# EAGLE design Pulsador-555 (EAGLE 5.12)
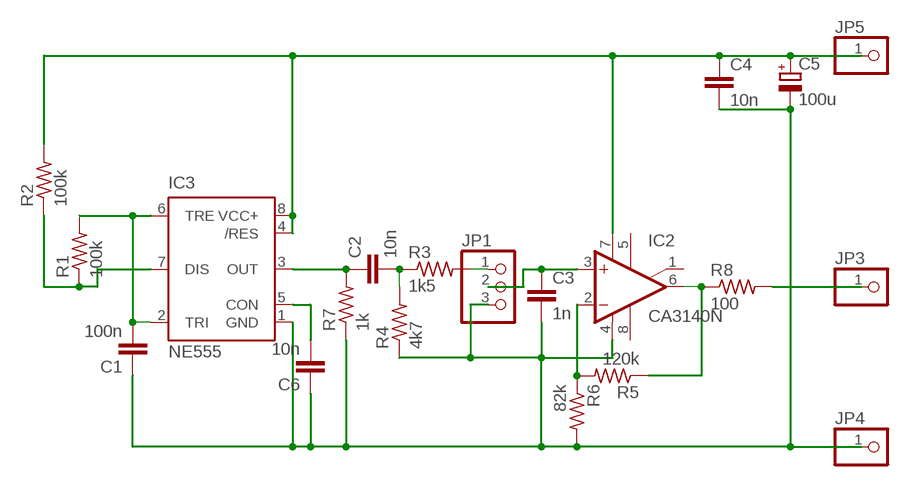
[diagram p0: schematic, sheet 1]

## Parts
C1  100n  C-EU050-024X044  [C050-024X044]
C2  10n  C-EU050-024X044  [C050-024X044]
C3  1n  C-EU050-024X044  [C050-024X044]
C4  10n  C-EU025-025X050  [C025-025X050]
C5  100u  CPOL-EUE3.5-10  [E3,5-10]
C6  10n  C-EU050-024X044  [C050-024X044]
IC2  CA3140N  [DIL08]
IC3  NE555  [DIL-08]
JP1  PINHD-1X3  [1X03]
JP3  PINHD-1X1  [1X01]
JP4  PINHD-1X1  [1X01]
JP5  PINHD-1X1  [1X01]
R1  100k  R-US_0204/7  [0204/7]
R2  100k  R-US_0204/7  [0204/7]
R3  1k5  R-US_0204/7  [0204/7]
R4  4k7  R-US_0204/7  [0204/7]
R5  120k  R-US_0204/7  [0204/7]
R6  82k  R-US_0204/7  [0204/7]
R7  1k  R-US_0204/7  [0204/7]
R8  100  R-US_0204/7  [0204/7]

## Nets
N$1: JP3.1 R8.2
N$2: C6.2 IC3.5(CON)
N$3: C2.1 IC3.3(OUT) R7.2
N$4: C2.2 R3.1 R4.2
N$5: C3.1 IC2.3(+IN) JP1.2
N$6: JP1.1 R3.2
N$7: IC2.6(OUT) R5.1 R8.1
N$8: IC2.2(-IN) R5.2 R6.1
N$9: IC3.7(DIS) R1.1 R2.1
N$10: C4.1 C5.+ IC2.7(V+) IC3.4(/RES) IC3.8(VCC+) JP5.1 R2.2
N$11: C1.2 IC3.2(TRI) IC3.6(TRE) R1.2
N$17: C1.1 C3.2 C4.2 C5.- C6.1 IC2.4(V-) IC3.1(GND) JP1.3 JP4.1 R4.1 R6.2 R7.1
Unconnected: IC2.1(ON/CMP) IC2.5(ON) IC2.8(CMP)

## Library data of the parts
C1-C4 C6 = rcl:C-EU: CAPACITOR, European symbol
C5 = rcl:CPOL-EU: POLARIZED CAPACITOR, European symbol
IC2 = linear:CA3140: OP AMP
IC3 = st-microelectronics:NE555: General purpose bipolar Timer; MF: Arrow Electronics; MPN: NE555N; OC_FARNELL: 1467742; OC_NEWARK: 89K1486
JP1 = pinhead:PINHD-1X3: PIN HEADER
JP3-JP5 = pinhead:PINHD-1X1: PIN HEADER
R1-R8 = rcl:R-US_: RESISTOR, American symbol

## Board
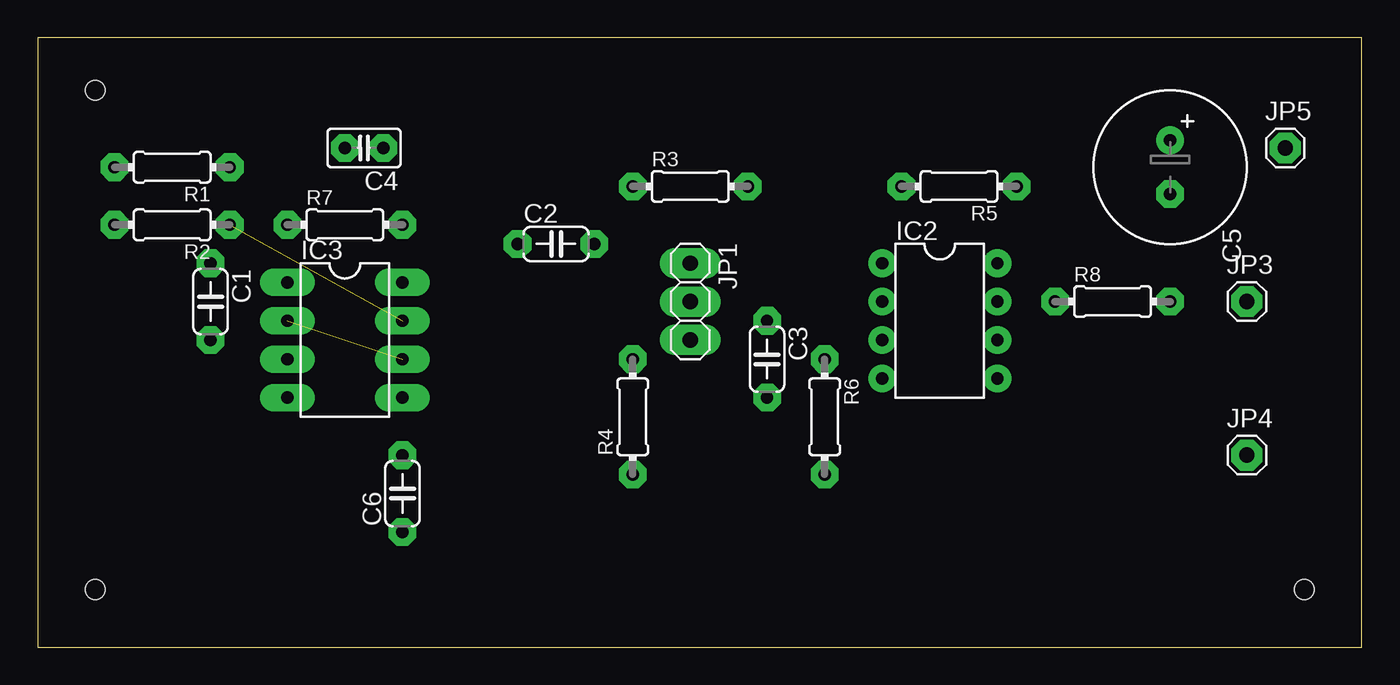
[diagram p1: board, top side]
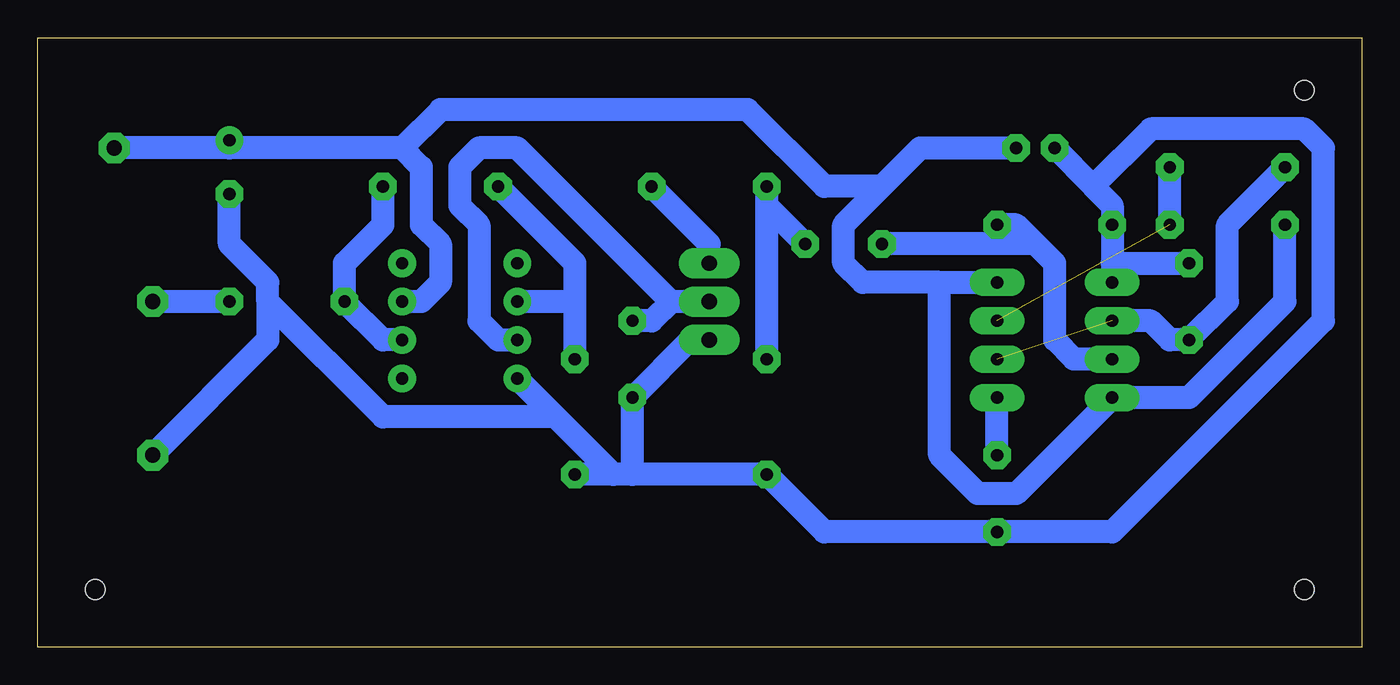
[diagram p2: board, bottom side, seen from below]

Size 87.61 x 40.31 mm. Coordinates in mm from the lower left corner, seen from the top.
Outline: 0,0 87.61,0 87.61,40.31 0,40.31 0,0
Copper layers (1*16): Top 0.035mm / dielectric 1.5mm / Bottom 0.035mm
Design rules "default *": minimum track width 60mil, minimum drill 24mil, track to track 20mil, track to pad 20mil, pad to pad 8mil, via to via 8mil, smd to smd 8mil, copper to edge 40mil, drill to drill 8mil, minimum pad ring 20mil, minimum via ring 8mil, stop-mask expansion 4mil, vias tented up to drill 0mil, thermal gap 10mil
Holes 1.3 mm at 3.81,36.83 3.81,3.81 83.82,3.81

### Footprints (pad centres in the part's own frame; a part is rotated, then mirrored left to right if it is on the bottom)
C050-024X044 = drill 0.813 octagon: 1 -2.54,0; 2 2.54,0
C025-025X050 = drill 0.813 octagon: 1 -1.27,0; 2 1.27,0
E3,5-10 = drill 0.813 pad 1.6 round: + -1.778,0 | drill 0.813 pad 1.6 octagon: - 1.778,0
DIL08 = drill 0.813 pad 1.27 round: 1 -3.81,-3.81; 2 -1.27,-3.81; 3 1.27,-3.81; 4 3.81,-3.81; 5 3.81,3.81; 6 1.27,3.81; 7 -1.27,3.81; 8 -3.81,3.81
DIL-08 = drill 0.813 long: 1 -3.81,-3.81; 2 -1.27,-3.81; 3 1.27,-3.81; 4 3.81,-3.81; 5 3.81,3.81; 6 1.27,3.81; 7 -1.27,3.81; 8 -3.81,3.81
1X03 = drill 1.016 long: 1 -2.54,0; 2 0,0; 3 2.54,0
1X01 = drill 1.016 octagon: 1 0,0
0204/7 = drill 0.813 octagon: 1 -3.81,0; 2 3.81,0

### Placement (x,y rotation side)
C1  11.43,22.86 270 top
C2  34.29,26.67 0 top
C3  48.26,19.05 270 top
C4  21.59,33.02 180 top
C5  74.93,31.75 270 top
C6  24.13,10.16 90 top
IC2  59.69,21.59 270 top
IC3  20.32,20.32 270 top
JP1  43.18,22.86 270 top
JP3  80.01,22.86 0 top
JP4  80.01,12.7 0 top
JP5  82.55,33.02 0 top
R1  8.89,31.75 180 top
R2  8.89,27.94 180 top
R3  43.18,30.48 0 top
R4  39.37,15.24 90 top
R5  60.96,30.48 180 top
R6  52.07,15.24 270 top
R7  20.32,27.94 0 top
R8  71.12,22.86 0 top

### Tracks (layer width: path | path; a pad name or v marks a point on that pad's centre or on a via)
N$1
  Bottom 1.524: R8.2 JP3.1
N$2
  Bottom 1.524: C6.2 IC3.5
N$3
  Bottom 1.524: IC3.3 19.05,19.05 20.32,20.32 20.32,25.4 21.59,26.67 | 21.59,26.67 22.86,27.94 R7.2 | 21.59,26.67 C2.1
N$4
  Bottom 1.524: 39.37,29.21 C2.2 | 39.37,29.21 R3.1 | R4.2 39.37,29.21
N$5
  Bottom 1.524: C3.1 46.99,21.59 45.72,22.86 | JP1.2 45.72,22.86 | IC2.3 57.15,20.32 58.42,21.59 58.42,27.94 59.69,29.21 59.69,31.75 58.42,33.02 55.88,33.02 45.72,22.86
N$6
  Bottom 1.524: R3.2 43.18,26.67 JP1.1
N$7
  Bottom 1.524: IC2.6 64.77,20.32 R8.1 67.31,25.4 64.77,27.94 R5.1
N$8
  Bottom 1.524: 52.07,22.86 52.07,25.4 R5.2 | R6.1 52.07,22.86 | 52.07,22.86 IC2.2
N$9  (1 unrouted)
  Bottom 1.524: R2.1 R1.1
N$10
  Bottom 1.524: R2.2 5.08,22.86 11.43,16.51 IC3.4 22.86,10.16 25.4,10.16 27.94,12.7 27.94,24.13 | C4.1 29.21,33.02 31.75,30.48 | 31.75,30.48 34.29,27.94 34.29,25.4 33.02,24.13 27.94,24.13 | 27.94,24.13 IC3.8 | IC2.7 62.23,22.86 60.96,24.13 60.96,26.67 62.23,27.94 62.23,31.75 63.5,33.02 | 63.5,33.02 74.93,33.02 | 74.93,33.02 JP5.1 | 74.93,33.02 C5.+ | 31.75,30.48 35.56,30.48 40.64,35.56 60.96,35.56 63.5,33.02
N$11  (1 unrouted)
  Bottom 1.524: IC3.2 13.97,21.59 12.7,20.32 C1.2 8.89,22.86 8.89,27.94 R1.2
N$17
  Bottom 1.524: 72.39,22.86 72.39,20.32 JP4.1 | 72.39,22.86 72.39,24.13 74.93,26.67 C5.- | 16.51,25.4 R7.1 16.51,29.21 17.78,30.48 | 16.51,25.4 IC3.1 | 16.51,25.4 C1.1 | 17.78,30.48 C4.2 | JP1.3 44.45,20.32 C3.2 48.26,11.43 | 48.26,11.43 R4.1 35.56,7.62 C6.1 16.51,7.62 2.54,21.59 2.54,33.02 3.81,34.29 13.97,34.29 17.78,30.48 | 48.26,11.43 49.53,11.43 | 49.53,11.43 R6.2 | 49.53,11.43 53.34,15.24 | 53.34,15.24 IC2.4 | 72.39,22.86 64.77,15.24 53.34,15.24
